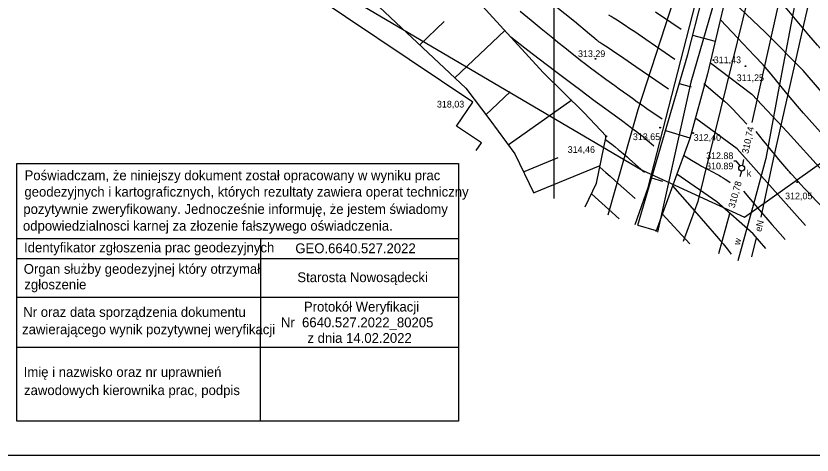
# Model space of a CAD drawing. Extents: x 7477803 to 7478145, y 5500698 to 5500984.
# Drawn here: x 7477945.2 to 7478026.3, y 5500697.6 to 5500742.3 of the extents above; entities that cross this region are included whole.
import ezdxf

# ---------------------------------------------------------------- set-up
doc = ezdxf.new("R2010")
doc.units = 0
for name, color, linetype in [('203-Punkt załamania granicy działki nie stabilizowany', 7, 'Continuous'), ('e_opisy', 7, 'Continuous'), ('e_Proj', 7, 'Continuous'), ('eNN', 7, 'Continuous'), ('gr_dzialki', 7, 'Continuous'), ('gr_klasy', 7, 'Continuous'), ('gr_uzytek', 7, 'Continuous'), ('jezdnia', 7, 'Continuous'), ('k', 7, 'Continuous'), ('k_elem_naziemne', 7, 'Continuous'), ('k_rzedne', 7, 'Continuous'), ('pkt_wys', 7, 'Continuous'), ('robocza11', 7, 'Continuous'), ('robocza49', 7, 'Continuous'), ('skarp_wypel', 7, 'Continuous'), ('skarpa_dol', 7, 'Continuous'), ('skarpa_gora', 7, 'Continuous'), ('t', 7, 'Continuous'), ('w', 7, 'Continuous'), ('w_opis', 7, 'Continuous'), ('warst_ciagla', 7, 'Continuous'), ('warst_pogrub', 7, 'Continuous'), ('warst_przeryw', 7, 'Continuous'), ('zakresy', 7, 'Continuous')]:
    doc.layers.add(name, color=color, linetype=linetype)

# ---------------------------------------------------------------- blocks, each defined once
blk = doc.blocks.new('203')
blk.add_circle((0, 0), 0.045)
blk = doc.blocks.new('506_5')
at = {"layer": 'k_elem_naziemne'}
blk.add_circle((0, 0), 0.3, dxfattribs=at)
blk = doc.blocks.new('140')
at = {"layer": 'pkt_wys'}
blk.add_circle((0, 0), 0.045, dxfattribs=at)
blk.add_circle((0, 0), 0.045, dxfattribs=at)
blk = doc.blocks.new('801')
at = {"layer": 'pkt_wys'}
blk.add_circle((0, 0), 0.045, dxfattribs=at)
blk.add_circle((0, 0), 0.045, dxfattribs=at)
blk = doc.blocks.new('801_5_3')
at = {"layer": 'pkt_wys'}
blk.add_circle((0, 0), 0.05, dxfattribs=at)
blk.add_circle((0, 0), 0.05, dxfattribs=at)

msp = doc.modelspace()

# ---------------------------------------------------------------- linework, layer by layer
for p, q in [((7477945.247, 5500719.634), (7477990.245, 5500719.634)), ((7477970.074, 5500719.634), (7477970.065, 5500701.011)), ((7477945.247, 5500717.571), (7477990.245, 5500717.571)), ((7477945.245, 5500713.641), (7477990.245, 5500713.641)), ((7477945.245, 5500713.641), (7477990.247, 5500713.641)), ((7477945.262, 5500708.541), (7477990.247, 5500708.541))]:
    msp.add_line(p, q)
msp.add_lwpolyline([(7477945.245, 5500727.263), (7477990.245, 5500727.263), (7477990.245, 5500701.011), (7477945.245, 5500701.011)], close=True)
at = {"layer": 'e_Proj'}
msp.add_lwpolyline([(7478085.721, 5500828.46), (7478062.59, 5500828.394), (7478057.723, 5500828.457), (7478045.093, 5500816.16), (7478029.949, 5500801.309), (7478024.948, 5500777.245), (7478020.357, 5500757.697), (7478013.921, 5500735.554), (7478010.536, 5500720.256)], dxfattribs=at)
at = {"layer": 'eNN'}
for points in [[(7478021.084, 5500721.798), (7478022.348, 5500727.709), (7478025.636, 5500742.267), (7478028.577, 5500754.673), (7478031.014, 5500765.159)], [(7478020.143, 5500717.75), (7478020.614, 5500719.696)]]:
    msp.add_lwpolyline(points, dxfattribs=at)
at = {"layer": 'gr_dzialki'}
for points in [[(7478009.6, 5500724.81), (7478019.23, 5500762.35)], [(7478008.27, 5500721.058), (7478009.6, 5500724.81)]]:
    msp.add_lwpolyline(points, dxfattribs=at)
at = {"layer": 'gr_klasy'}
for points in [[(7478009.6, 5500724.81), (7478019.23, 5500762.35)], [(7478008.27, 5500721.058), (7478009.6, 5500724.81)]]:
    msp.add_lwpolyline(points, dxfattribs=at)
at = {"layer": 'gr_uzytek'}
msp.add_lwpolyline([(7478030.57, 5500778.31), (7478022.71, 5500756.1), (7478014.63, 5500723.4), (7478013.163, 5500719.326)], dxfattribs=at)
at = {"layer": 'jezdnia'}
msp.add_lwpolyline([(7477992.069, 5500728.595), (7477992.586, 5500729.366), (7477990.061, 5500731.06), (7477991.702, 5500733.507), (7477933.306, 5500772.671), (7477931.61, 5500770.142), (7477929.08, 5500771.838), (7477927.439, 5500769.391), (7477926.244, 5500770.192), (7477925.336, 5500768.842)], dxfattribs=at)
at = {"layer": 'k'}
for p, q in [((7478029.096, 5500771.195), (7478020.147, 5500731.456)), ((7478019.311, 5500727.655), (7478019.185, 5500727.081)), ((7478019.086, 5500726.492), (7478018.922, 5500725.899)), ((7478017.876, 5500722.13), (7478016.746, 5500718.058))]:
    msp.add_line(p, q, dxfattribs=at)
at = {"layer": 'k_rzedne'}
msp.add_lwpolyline([(7478018.325, 5500727.531), (7478018.506, 5500727.531), (7478018.922, 5500727.023)], dxfattribs=at)
at = {"layer": 'robocza11'}
msp.add_lwpolyline([(7478014.996, 5500697.565), (7478144.729, 5500697.565), (7478144.729, 5500983.565), (7477803.256, 5500983.565), (7477803.256, 5500697.565), (7478010.821, 5500697.565)], close=True, dxfattribs=at)
at = {"layer": 'robocza49'}
msp.add_line((7478000, 5500723.706), (7478000, 5500750), dxfattribs=at)
at = {"layer": 'skarp_wypel'}
for p, q in [((7477986.302, 5500739.359), (7477988.788, 5500741.712)), ((7477989.885, 5500735.988), (7477994.976, 5500740.805)), ((7478014.117, 5500740.327), (7478016.421, 5500739.734)), ((7478012.753, 5500735.426), (7478013.962, 5500735.073)), ((7477993.05, 5500732.221), (7477995.529, 5500734.567)), ((7477995.316, 5500729.174), (7478001.805, 5500733.744)), ((7478011.346, 5500730.609), (7478013.839, 5500729.88)), ((7477996.881, 5500726.423), (7478000.413, 5500727.86)), ((7477997.909, 5500724.286), (7478004.689, 5500727.045)), ((7478009.939, 5500725.791), (7478011.033, 5500725.472)), ((7478008.532, 5500720.974), (7478010.406, 5500720.427))]:
    msp.add_line(p, q, dxfattribs=at)
at = {"layer": 'skarpa_dol'}
msp.add_lwpolyline([(7478003.179, 5500722.859), (7478004.323, 5500725.251), (7478005.298, 5500730.032), (7478003.066, 5500732.439), (7477998.881, 5500736.525), (7477989.029, 5500747.324), (7477982.233, 5500752.776), (7477973.187, 5500758.837), (7477956.935, 5500769.599), (7477950.58, 5500774.332), (7477941.825, 5500778.562), (7477933.581, 5500781.953), (7477926.713, 5500780.256), (7477921.899, 5500775.451), (7477920.234, 5500772.903)], dxfattribs=at)
at = {"layer": 'skarpa_gora'}
for points in [[(7478008.529, 5500720.966), (7478013.614, 5500738.374), (7478016.556, 5500749.806), (7478020.275, 5500763.382), (7478022.118, 5500770.559), (7478023.375, 5500778.71), (7478024.881, 5500786.965)], [(7478024.881, 5500786.965), (7478024.924, 5500787.202), (7478024.325, 5500770.813), (7478019.007, 5500749.589), (7478017.956, 5500746.211), (7478015.629, 5500736.387), (7478013.818, 5500729.802), (7478010.366, 5500720.316)], [(7477924.585, 5500769.172), (7477928.36, 5500773.878), (7477930.919, 5500774.6), (7477933.4, 5500774.083), (7477944.537, 5500767.355), (7477948.908, 5500766.44), (7477961.969, 5500756.974), (7477978.9, 5500746.323), (7477991.003, 5500734.936), (7477993.436, 5500731.709), (7477996, 5500728.251), (7477997.928, 5500724.248)]]:
    msp.add_lwpolyline(points, dxfattribs=at)
at = {"layer": 't'}
msp.add_lwpolyline([(7478005.519, 5500722.031), (7478006.224, 5500724.533), (7478008.555, 5500732.765), (7478012.721, 5500745.54), (7478013.655, 5500748.332)], dxfattribs=at)
at = {"layer": 'w'}
msp.add_lwpolyline([(7478028.928, 5500766.534), (7478026.087, 5500751.628), (7478024.78, 5500744.808), (7478022.827, 5500734.611), (7478021.568, 5500727.759), (7478020.307, 5500723.115), (7478018.729, 5500717.357)], dxfattribs=at)
at = {"layer": 'warst_ciagla'}
for points in [[(7478011.649, 5500734.85), (7478008.326, 5500737.122), (7478007.088, 5500737.967), (7478005.947, 5500738.743), (7478005.498, 5500739.046), (7478004.968, 5500739.4), (7478004.67, 5500739.589), (7478004.599, 5500739.636), (7478004.494, 5500739.711), (7478004.438, 5500739.753), (7478004.348, 5500739.823), (7478004.219, 5500739.926), (7478004.15, 5500739.983), (7478003.614, 5500740.431), (7478002.063, 5500741.714), (7477999.307, 5500743.984), (7477995.668, 5500746.981), (7477994.123, 5500748.258), (7477993.37, 5500748.883), (7477992.227, 5500749.834), (7477990.687, 5500751.121), (7477990, 5500751.698), (7477989.207, 5500752.369)], [(7478012.95, 5500740.899), (7478011.909, 5500741.611), (7478010.345, 5500742.676)], [(7478031.728, 5500725.344), (7478028.574, 5500728.864), (7478025.419, 5500732.384), (7478024.786, 5500733.107), (7478023.709, 5500734.4), (7478022.106, 5500736.352), (7478021.285, 5500737.309), (7478020.432, 5500738.239), (7478018.703, 5500740.05), (7478016.973, 5500741.861)], [(7478010.145, 5500729.045), (7478009.891, 5500729.27), (7478009.734, 5500729.407), (7478009.446, 5500729.653), (7478009.313, 5500729.764), (7478009.065, 5500729.967), (7478008.835, 5500730.15), (7478008.688, 5500730.263), (7478008.404, 5500730.481), (7478007.919, 5500730.845), (7478007.583, 5500731.096), (7478006.858, 5500731.631), (7478004.911, 5500733.056), (7478004.198, 5500733.58), (7478003.214, 5500734.311), (7478002.707, 5500734.689), (7478001.929, 5500735.272), (7478000.855, 5500736.081), (7478000.304, 5500736.498), (7477999.178, 5500737.354), (7477998.611, 5500737.788), (7477997.769, 5500738.434), (7477997.026, 5500739.009), (7477996.064, 5500739.758), (7477995.596, 5500740.126)], [(7478015.252, 5500735.422), (7478016.659, 5500734.221), (7478017.357, 5500733.614), (7478017.698, 5500733.303), (7478018.033, 5500732.985), (7478018.24, 5500732.778), (7478018.594, 5500732.405), (7478019.627, 5500731.259)], [(7478028.438, 5500721.65), (7478027.837, 5500722.277), (7478027.236, 5500722.904), (7478026.637, 5500723.532), (7478026.04, 5500724.162), (7478025.446, 5500724.795), (7478024.857, 5500725.433), (7478024.565, 5500725.754), (7478024.274, 5500726.076), (7478024.129, 5500726.237), (7478023.985, 5500726.399), (7478023.913, 5500726.48), (7478023.841, 5500726.561), (7478023.769, 5500726.642), (7478023.697, 5500726.724), (7478023.296, 5500727.188), (7478022.9, 5500727.657), (7478022.509, 5500728.13), (7478022.122, 5500728.606), (7478021.737, 5500729.084), (7478021.351, 5500729.562), (7478020.965, 5500730.039), (7478020.576, 5500730.515)], [(7478005.235, 5500729.72), (7478005.66, 5500729.393), (7478005.878, 5500729.222), (7478006.219, 5500728.951), (7478006.529, 5500728.702), (7478006.708, 5500728.553), (7478007.03, 5500728.282), (7478007.437, 5500727.932), (7478007.68, 5500727.72), (7478008.263, 5500727.208), (7478008.609, 5500726.901), (7478009.205, 5500726.37)], [(7478013.193, 5500728.101), (7478014.007, 5500727.611), (7478014.821, 5500727.121), (7478015.019, 5500727.004), (7478015.169, 5500726.919), (7478015.396, 5500726.795), (7478015.624, 5500726.674), (7478016.135, 5500726.405), (7478016.646, 5500726.136)], [(7478016.646, 5500726.136), (7478016.846, 5500726.025), (7478016.995, 5500725.939), (7478017.215, 5500725.806), (7478017.323, 5500725.737), (7478017.431, 5500725.667), (7478017.685, 5500725.498), (7478017.939, 5500725.328)], [(7478012.062, 5500724.983), (7478014.301, 5500722.428), (7478016.539, 5500719.872), (7478016.925, 5500719.423), (7478017.209, 5500719.082), (7478017.629, 5500718.565), (7478018.041, 5500718.042)], [(7478019.296, 5500724.449), (7478020.737, 5500722.757), (7478022.179, 5500721.064), (7478022.516, 5500720.676), (7478023.031, 5500720.104), (7478023.555, 5500719.539)]]:
    msp.add_lwpolyline(points, dxfattribs=at)
at = {"layer": 'warst_pogrub'}
for points in [[(7478027.721, 5500738.329), (7478026.825, 5500739.318), (7478026.384, 5500739.82), (7478025.952, 5500740.329), (7478023.747, 5500742.986), (7478021.542, 5500745.643)], [(7478004.658, 5500726.891), (7478005.287, 5500726.341), (7478005.715, 5500725.963), (7478006.537, 5500725.235), (7478008.264, 5500723.696)]]:
    msp.add_lwpolyline(points, dxfattribs=at)
at = {"layer": 'warst_przeryw'}
for points in [[(7478032.47, 5500728.495), (7478028.924, 5500732.62), (7478025.371, 5500736.739), (7478021.544, 5500740.607), (7478017.614, 5500744.368)], [(7477996.537, 5500742.775), (7477997.654, 5500741.857), (7477998.674, 5500741.022), (7477999.864, 5500740.05), (7478000.387, 5500739.625), (7478001.079, 5500739.064), (7478001.834, 5500738.458), (7478002.138, 5500738.215), (7478002.511, 5500737.922), (7478002.721, 5500737.76), (7478003.107, 5500737.467), (7478003.411, 5500737.239), (7478003.852, 5500736.91), (7478004.089, 5500736.734), (7478005.283, 5500735.857), (7478006.179, 5500735.204), (7478006.63, 5500734.878), (7478007.516, 5500734.242), (7478007.988, 5500733.907), (7478008.477, 5500733.562), (7478008.801, 5500733.337), (7478009.457, 5500732.883), (7478010.999, 5500731.825)], [(7478012.3, 5500737.874), (7478009.336, 5500739.899), (7478008.211, 5500740.664), (7478007.726, 5500740.993), (7478007.125, 5500741.394), (7478006.661, 5500741.701), (7478006.413, 5500741.862), (7478006.032, 5500742.104), (7478005.814, 5500742.237), (7478005.567, 5500742.388)], [(7478015.927, 5500737.523), (7478020.144, 5500734.31), (7478023.794, 5500730.471), (7478027.35, 5500726.525), (7478030.118, 5500723.588)], [(7478025.62, 5500720.956), (7478022.252, 5500724.704), (7478018.662, 5500728.769), (7478014.428, 5500731.862)], [(7478021.579, 5500718.591), (7478020.291, 5500720.092), (7478016.592, 5500723.372), (7478012.501, 5500726.17)], [(7478006.634, 5500721.636), (7478003.803, 5500724.163)], [(7478013.842, 5500719.086), (7478011.015, 5500722.136)]]:
    msp.add_lwpolyline(points, dxfattribs=at)
at = {"layer": 'zakresy'}
msp.add_lwpolyline([(7477995.059, 5500962.348), (7477983.951, 5500968.084), (7477970.781, 5500968.613), (7477936.09, 5500958.171), (7477930.511, 5500954.336), (7477914.305, 5500958.58), (7477904.32, 5500957.41), (7477897.265, 5500950.868), (7477811.424, 5500829.338), (7477936.003, 5500769.492), (7478008.982, 5500726.585), (7478019.402, 5500721.781), (7478037.95, 5500734.97), (7478039.493, 5500755.094), (7478043.98, 5500765.708), (7478067.545, 5500795.068), (7478092.109, 5500820.25), (7478076.156, 5500837.989), (7478068.105, 5500851.146), (7478061.422, 5500873.298), (7478054.135, 5500876.371), (7478039.669, 5500897.644), (7478026.36, 5500915.23), (7478015.054, 5500927.728)], close=True, dxfattribs=at)

# ---------------------------------------------------------------- block references
at = {"layer": '203-Punkt załamania granicy działki nie stabilizowany'}
msp.add_blockref('203', (7478009.6, 5500724.81), dxfattribs=at)
at = {"layer": 'k_elem_naziemne', "rotation": 0.0626175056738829}
msp.add_blockref('506_5', (7478019.112, 5500726.79), dxfattribs=at)
at = {"layer": 'pkt_wys', "rotation": 0.0626175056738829}
for name, p in [('801', (7478004.22, 5500737.92)), ('140', (7478016.234, 5500737.801)), ('140', (7478019.504, 5500737.178)), ('140', (7478010.804, 5500730.918)), ('801_5_3', (7478005.298, 5500730.032)), ('140', (7478014.175, 5500730.362)), ('140', (7478024.768, 5500725.36))]:
    msp.add_blockref(name, p, dxfattribs=at)

# ---------------------------------------------------------------- texts
for s, p in [('Poświadczam, że niniejszy dokument został opracowany w wyniku prac', (7477946.04, 5500725.564)), ('geodezyjnych i kartograficznych, których rezultaty zawiera operat techniczny', (7477946.026, 5500723.887)), ('pozytywnie zweryfikowany. Jednocześnie informuję, że jestem świadomy', (7477945.917, 5500722.124)), ('odpowiedzialnosci karnej za złozenie fałszywego oświadczenia.', (7477945.877, 5500720.422)), ('Identyfikator zgłoszenia prac geodezyjnych', (7477945.99, 5500718.209)), ('GEO.6640.527.2022', (7477973.63, 5500718.126)), ('Organ służby geodezyjnej który otrzymał', (7477945.96, 5500716.029)), ('Starosta Nowosądecki', (7477973.837, 5500715.179)), ('zgłoszenie', (7477946.02, 5500714.446)), ('Protokół Weryfikacji', (7477974.505, 5500712.182)), ('Nr oraz data sporządzenia dokumentu', (7477945.909, 5500711.64)), ('Nr  6640.527.2022_80205', (7477972.161, 5500710.578)), ('zawierającego wynik pozytywnej weryfikacji', (7477945.789, 5500709.873)), ('z dnia 14.02.2022', (7477974.865, 5500708.988)), ('Imię i nazwisko oraz nr uprawnień', (7477945.956, 5500705.532)), ('zawodowych kierownika prac, podpis', (7477945.987, 5500703.676))]:
    msp.add_text(s, height=1).set_placement(p)
at = {"layer": 'e_opisy'}
msp.add_text('eN', height=0.68, rotation=76.37743, dxfattribs=at).set_placement((7478021.102, 5500720.264))
at = {"layer": 'k_elem_naziemne'}
msp.add_text('k', height=0.68, rotation=0.06262, dxfattribs=at).set_placement((7478019.632, 5500725.936))
at = {"layer": 'k_rzedne'}
for s, rotation, p in [('310,74', 77.60188, (7478019.782, 5500728.215)), ('312.88', 0.06262, (7478015.484, 5500727.708)), ('310.89', 0.06262, (7478015.485, 5500726.668)), ('310,78', 74.49084, (7478018.381, 5500722.679))]:
    msp.add_text(s, height=0.68, rotation=rotation, dxfattribs=at).set_placement(p)
at = {"layer": 'pkt_wys'}
for s, p in [('313.29', (7478002.435, 5500738.103)), ('311,43', (7478016.266, 5500737.481)), ('311,25', (7478018.606, 5500735.654)), ('318,03', (7477988.062, 5500732.966)), ('313,65', (7478008.026, 5500729.646)), ('312,40', (7478014.227, 5500729.572)), ('314,46', (7478001.385, 5500728.347)), ('312,05', (7478023.537, 5500723.618))]:
    msp.add_text(s, height=0.68, rotation=0.06262, dxfattribs=at).set_placement(p)
at = {"layer": 'w_opis'}
msp.add_text('w', height=0.68, rotation=74.68142, dxfattribs=at).set_placement((7478018.92, 5500718.909))

doc.saveas('drawing.dxf')
